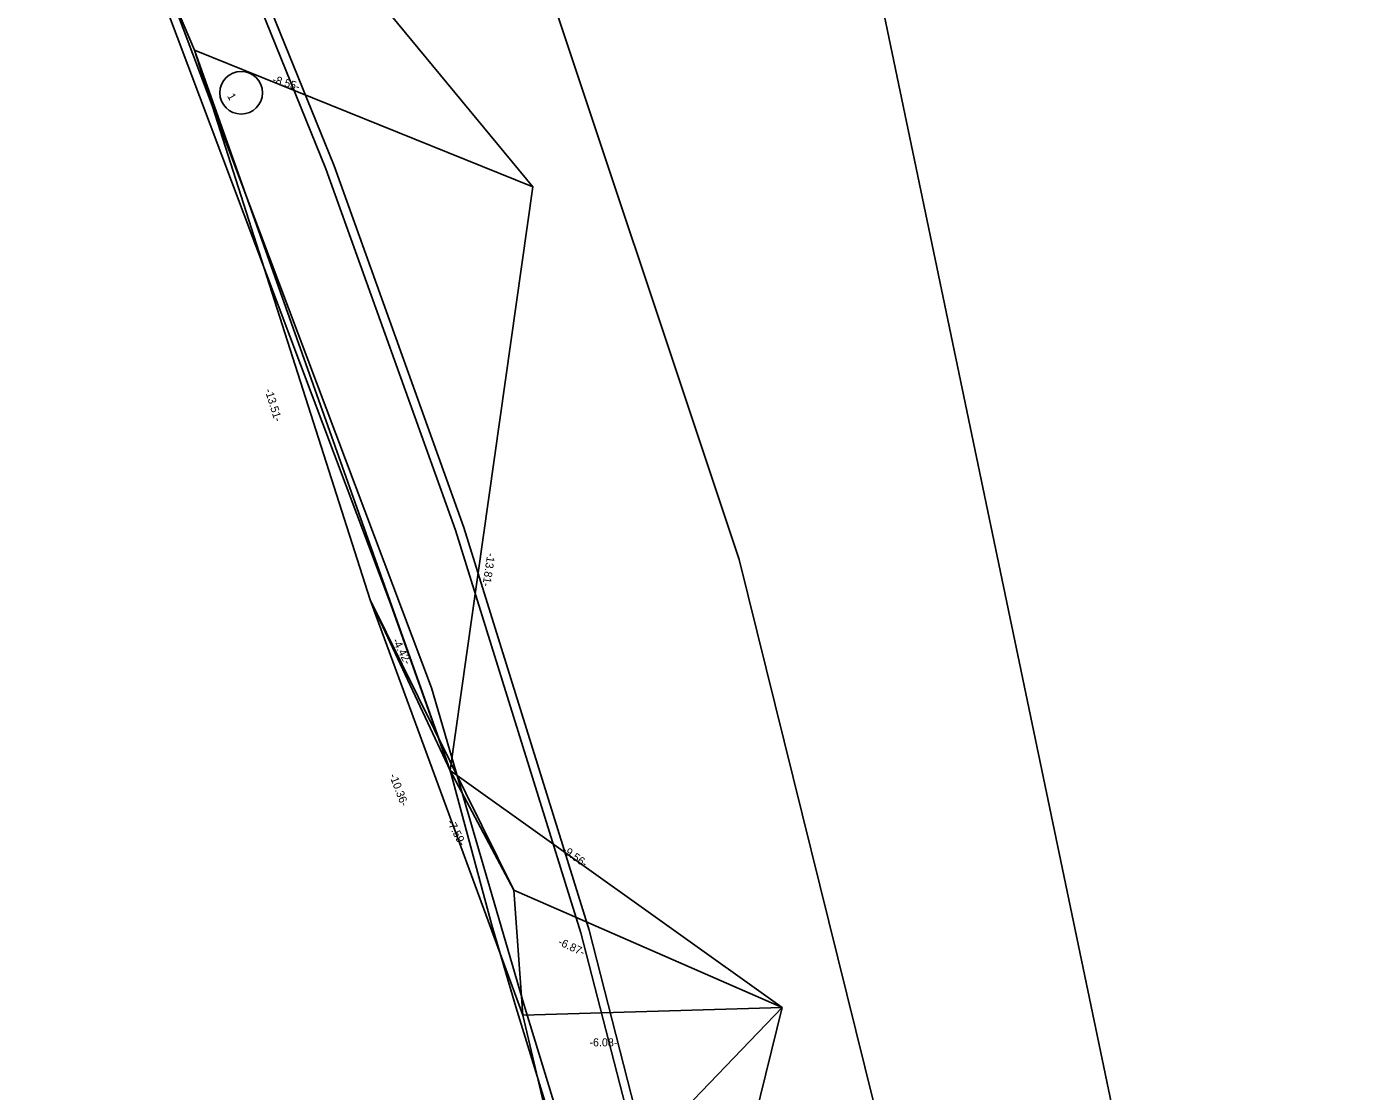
# Model space of a CAD drawing. Extents: x -597791 to -597535, y -1159670 to -1159547.
# Drawn here: x -597686.05 to -597654.67, y -1159631.67 to -1159606.74 of the extents above; entities that cross this region are included whole.
import ezdxf

# ---------------------------------------------------------------- set-up
doc = ezdxf.new("R2010")
doc.units = 0
for name, color, linetype in [('Koordinační kabel-Pom_KK Metalic', 7, 'Continuous'), ('Koordinační kabel-Pom_Oměrná KKM', 7, 'Continuous'), ('Koordinační kabel-Pom_Text KKM', 7, 'Continuous'), ('MAPA', 7, 'Continuous'), ('Žádosti', 7, 'Continuous')]:
    doc.layers.add(name, color=color, linetype=linetype)

msp = doc.modelspace()

# ---------------------------------------------------------------- linework, layer by layer
at = {"layer": 'Koordinační kabel-Pom_KK Metalic'}
msp.add_lwpolyline([(-597673.151, -1159662.001), (-597672.53, -1159646.67), (-597673.26, -1159634.82), (-597674.43, -1159629.89), (-597674.64, -1159626.96), (-597676.13, -1159624.16), (-597682.12, -1159607.29), (-597687.7, -1159594.16), (-597695.09, -1159580.13), (-597702.91, -1159567.07), (-597713.779, -1159550.637)], dxfattribs=at)
at = {"layer": 'Koordinační kabel-Pom_Oměrná KKM'}
for points in [[(-597687.7, -1159594.16), (-597674.19, -1159610.49)], [(-597674.19, -1159610.49), (-597682.12, -1159607.29)], [(-597682.12, -1159607.29), (-597678, -1159620.16)], [(-597676.13, -1159624.16), (-597674.19, -1159610.49)], [(-597676.13, -1159624.16), (-597678, -1159620.16)], [(-597678, -1159620.16), (-597674.64, -1159626.96)], [(-597674.43, -1159629.89), (-597678, -1159620.16)], [(-597668.35, -1159629.71), (-597676.13, -1159624.16)], [(-597674.64, -1159626.96), (-597668.35, -1159629.71)], [(-597668.35, -1159629.71), (-597674.43, -1159629.89)], [(-597668.35, -1159629.71), (-597673.26, -1159634.82)], [(-597672.53, -1159646.67), (-597668.35, -1159629.71)]]:
    msp.add_lwpolyline(points, dxfattribs=at)
at = {"layer": 'Koordinační kabel-Pom_Text KKM'}
msp.add_circle((-597681.024, -1159608.284), 0.5, dxfattribs=at)
at = {"layer": 'MAPA'}
for points in [[(-597704.593, -1159549.561), (-597696.83, -1159561.36), (-597686.72, -1159577.97), (-597680.02, -1159590.93), (-597674.28, -1159604.46), (-597669.36, -1159619.22), (-597665.99, -1159632.8), (-597665.39, -1159635.96)], [(-597684.99, -1159600.98), (-597682.8, -1159606.25), (-597677.52, -1159620.27)], [(-597684.81, -1159600.9), (-597682.61, -1159606.18), (-597676.57, -1159622.22)], [(-597682.09, -1159602.55), (-597679.04, -1159610.07), (-597676, -1159618.53), (-597673.07, -1159627.96), (-597671.9, -1159632.5)], [(-597681.9, -1159602.47), (-597678.85, -1159610), (-597675.81, -1159618.47), (-597672.87, -1159627.9), (-597671.71, -1159632.45)], [(-597673.57, -1159633.02), (-597674.59, -1159629.69), (-597675.15, -1159627.78), (-597676.11, -1159624.21), (-597677.52, -1159620.27)], [(-597673.38, -1159632.97), (-597674.4, -1159629.63), (-597676.57, -1159622.22)]]:
    msp.add_lwpolyline(points, dxfattribs=at)
at = {"layer": 'Žádosti'}
msp.add_lwpolyline([(-597654.67, -1159660.54), (-597678.483, -1159546.504), (-597791.46, -1159559.733), (-597772.145, -1159668.212), (-597768.441, -1159669.535)], close=True, dxfattribs=at)

# ---------------------------------------------------------------- texts
at = {"layer": 'Koordinační kabel-Pom_Oměrná KKM'}
for s, rotation, p in [('-8.55-', 343.485, (-597680.31, -1159608.05)), ('-13.51-', 287.2382, (-597680.474, -1159615.246)), ('-13.81-', 261.5217, (-597675.256, -1159619.054)), ('-4.42-', 297.2865, (-597677.49, -1159621.115)), ('-10.36-', 291.0547, (-597677.558, -1159624.273)), ('-7.59-', 297.2865, (-597676.211, -1159625.362)), ('-9.56-', 324.1896, (-597673.522, -1159626.054)), ('-6.87-', 334.8814, (-597673.618, -1159628.233)), ('-6.08-', 359.6789, (-597672.867, -1159630.617))]:
    msp.add_text(s, height=0.1875, rotation=rotation, dxfattribs=at).set_placement(p)
at = {"layer": 'Koordinační kabel-Pom_Text KKM'}
msp.add_text('1', height=0.188, rotation=300.2, dxfattribs=at).set_placement((-597681.36, -1159608.362))

doc.saveas('drawing.dxf')
